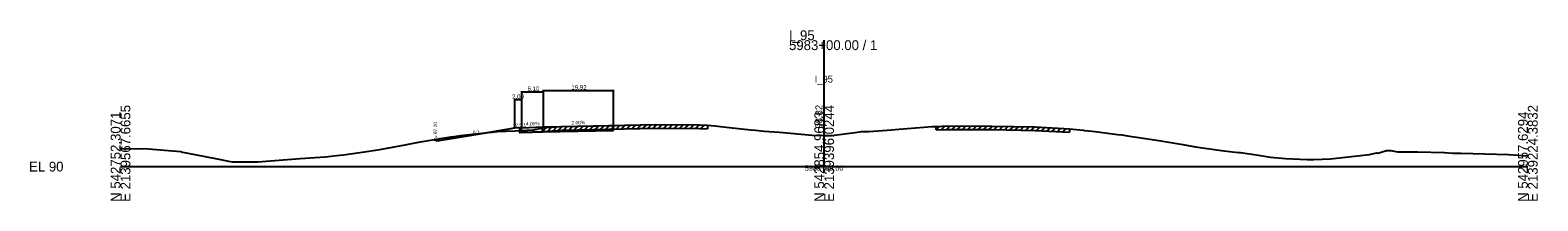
# Model space of a CAD drawing. Extents: x -12534 to 3403, y -1332 to 21983.
# Drawn here: x -25.7 to 402.8, y 14990.3 to 15038.7 of the extents above; entities that cross this region are included whole.
import ezdxf

# ---------------------------------------------------------------- set-up
doc = ezdxf.new("R2010")
doc.units = 0
for name, color, linetype in [('RD_GPK_XS_Cell', 7, 'Continuous'), ('RD_XD_TX_Width', 7, 'Continuous'), ('RD_XS_Base', 7, 'Continuous'), ('RD_XS_EarthShd', 7, 'Continuous'), ('RD_XS_EwShp', 7, 'Continuous'), ('RD_XS_ExGround', 7, 'Continuous'), ('RD_XS_ExPaveRet', 7, 'Continuous'), ('RD_XS_OSBase', 7, 'Continuous'), ('RD_XS_Pave', 7, 'Continuous'), ('RD_XS_TieSlope', 7, 'Continuous'), ('RD_XS_TX_Baseline', 7, 'Continuous'), ('RD_XS_TX_Elev_EX', 7, 'Continuous'), ('RD_XS_TX_Elev_PR', 7, 'Continuous'), ('RD_XS_TX_ShdSlope', 7, 'Continuous'), ('RD_XS_TX_Slope', 7, 'Continuous'), ('RD_XS_TX_Station', 7, 'Continuous')]:
    doc.layers.add(name, color=color, linetype=linetype)

msp = doc.modelspace()

# ---------------------------------------------------------------- linework, layer by layer
at = {"layer": 'RD_GPK_XS_Cell'}
for p, q in [((200, 15000), (200, 15035.85)), ((0, 15000), (200, 15000)), ((200, 15000), (400, 15000))]:
    msp.add_line(p, q, dxfattribs=at)
at = {"layer": 'RD_XD_TX_Width'}
for p, q in [((113.98, 15021.42), (113.98, 15011.23)), ((113.98, 15021.22), (120.08, 15021.22)), ((120.08, 15021.82), (120.08, 15011.47)), ((120.08, 15021.62), (140, 15021.62)), ((120.08, 15021.42), (120.08, 15011.47)), ((140, 15021.82), (140, 15011.87)), ((111.98, 15019.18), (111.98, 15011.07)), ((113.98, 15018.98), (111.98, 15018.98)), ((113.98, 15019.18), (113.98, 15011.23))]:
    msp.add_line(p, q, dxfattribs=at)
at = {"layer": 'RD_XS_Base'}
for p, q in [((113.98, 15009.63), (120.08, 15009.87)), ((120.08, 15009.87), (140, 15010.27))]:
    msp.add_line(p, q, dxfattribs=at)
at = {"layer": 'RD_XS_EarthShd'}
msp.add_line((113.98, 15011.03), (111.98, 15010.87), dxfattribs=at)
at = {"layer": 'RD_XS_EwShp'}
for points in [[(113.98, 15009.63), (113.48, 15009.61), (113.48, 15010.22), (117.47, 15010.47), (119.93, 15010.98), (125.46, 15011.34), (140, 15011.67), (140, 15011.27), (140, 15010.27), (120.08, 15009.87)], [(93.84, 15008.43), (94.79, 15008.58), (96.67, 15008.78), (105.23, 15009.78), (105.65, 15009.81), (89.98, 15007.2), (89.13, 15007.63), (90.93, 15007.93)], [(113.48, 15010.22), (113.48, 15010.61), (113.98, 15010.63), (113.98, 15011.03), (111.98, 15010.87), (105.65, 15009.81), (107.1, 15009.93), (112.14, 15010.13)]]:
    msp.add_lwpolyline(points, close=True, dxfattribs=at)
at = {"layer": 'RD_XS_ExGround'}
msp.add_lwpolyline([(0, 15005.03), (6.83, 15005.15), (13.67, 15004.58), (17.12, 15004.26), (17.64, 15004.1), (21.07, 15003.46), (27.5, 15002.16), (30.72, 15001.53), (31.85, 15001.37), (35.82, 15001.36), (39.02, 15001.32), (51.02, 15002.29), (58.19, 15002.8), (62.32, 15003.2), (63.35, 15003.33), (68.72, 15004.08), (73.73, 15004.87), (80.9, 15006.19), (84.23, 15006.81), (85.87, 15007.09), (90.93, 15007.93), (93.84, 15008.43), (94.79, 15008.58), (96.67, 15008.78), (105.23, 15009.78), (107.1, 15009.93), (112.14, 15010.13), (117.47, 15010.47), (119.93, 15010.98), (125.46, 15011.34), (152.11, 15011.95), (164.56, 15011.83), (166.87, 15011.73), (168.93, 15011.56), (172.98, 15011.11), (179.13, 15010.44), (180.48, 15010.32), (182.96, 15010.09), (187.25, 15009.73), (196.61, 15008.93), (200.27, 15008.81), (202.06, 15008.82), (208.8, 15009.69), (210.61, 15009.94), (211.55, 15009.99), (212.81, 15009.99), (219.15, 15010.46), (221.24, 15010.62), (228.34, 15011.21), (230.72, 15011.39), (231.8, 15011.42), (235.1, 15011.55), (247.68, 15011.51), (259.95, 15011.28), (269.69, 15010.74), (273.62, 15010.35), (273.98, 15010.29), (275.19, 15010.19), (277.05, 15010), (283.41, 15009.14), (284.58, 15009), (286.23, 15008.71), (295.07, 15007.42), (301.92, 15006.26), (305.51, 15005.64), (312.92, 15004.59), (316.01, 15004.17), (317.87, 15004), (318.33, 15003.96), (323.44, 15003.24), (326.81, 15002.7), (331.13, 15002.28), (337.26, 15002.05), (339.19, 15002.06), (343.94, 15002.22), (354.96, 15003.44), (357, 15003.94), (357.39, 15003.81), (359.78, 15004.58), (360.23, 15004.6), (361.04, 15004.54), (362.98, 15004.18), (368.66, 15004.22), (376.34, 15004.02), (378.68, 15003.82), (379.47, 15003.82), (381.03, 15003.8), (394.46, 15003.41), (400, 15003.05)], dxfattribs=at)
at = {"layer": 'RD_XS_ExPaveRet'}
for p, q in [((131.93, 15010.49), (132.95, 15011.51)), ((133.43, 15010.52), (134.45, 15011.54)), ((134.93, 15010.56), (135.95, 15011.58)), ((136.43, 15010.59), (137.45, 15011.61)), ((137.93, 15010.62), (138.95, 15011.65)), ((139.43, 15010.66), (140.45, 15011.68)), ((140.93, 15010.69), (141.95, 15011.72)), ((142.43, 15010.73), (143.45, 15011.75)), ((143.93, 15010.76), (144.95, 15011.79)), ((145.43, 15010.8), (146.45, 15011.82)), ((146.93, 15010.83), (147.95, 15011.85)), ((148.43, 15010.86), (149.45, 15011.89)), ((149.93, 15010.9), (150.95, 15011.92)), ((151.43, 15010.93), (152.44, 15011.95)), ((152.93, 15010.94), (153.92, 15011.93)), ((154.43, 15010.93), (155.42, 15011.92)), ((155.93, 15010.91), (156.92, 15011.9)), ((157.43, 15010.9), (158.42, 15011.89)), ((158.93, 15010.88), (159.92, 15011.87)), ((160.43, 15010.87), (161.42, 15011.86)), ((161.93, 15010.85), (162.92, 15011.84)), ((163.43, 15010.84), (164.42, 15011.83)), ((164.93, 15010.81), (165.89, 15011.77)), ((166.87, 15011.73), (166.87, 15010.73)), ((233.3, 15010.48), (234.34, 15011.52)), ((234.8, 15010.54), (235.81, 15011.55)), ((236.3, 15010.55), (237.29, 15011.55)), ((237.8, 15010.54), (238.79, 15011.54)), ((239.3, 15010.54), (240.29, 15011.54)), ((240.8, 15010.53), (241.79, 15011.53)), ((242.3, 15010.53), (243.29, 15011.53)), ((243.8, 15010.53), (244.79, 15011.52)), ((245.3, 15010.52), (246.29, 15011.52)), ((246.8, 15010.52), (247.79, 15011.51)), ((119.93, 15009.98), (121, 15011.05)), ((119.93, 15009.98), (119.93, 15010.98)), ((119.93, 15009.98), (125.46, 15010.34)), ((121.43, 15010.08), (122.5, 15011.15)), ((122.93, 15010.18), (124, 15011.24)), ((124.43, 15010.27), (125.5, 15011.34)), ((125.46, 15010.34), (152.11, 15010.95)), ((125.93, 15010.35), (126.95, 15011.37)), ((127.43, 15010.38), (128.45, 15011.41)), ((128.93, 15010.42), (129.95, 15011.44)), ((130.43, 15010.45), (131.45, 15011.48)), ((152.11, 15010.95), (164.56, 15010.83)), ((164.56, 15010.83), (166.87, 15010.73)), ((231.8, 15010.42), (232.84, 15011.46)), ((231.8, 15010.42), (231.8, 15011.42)), ((231.8, 15010.42), (235.1, 15010.55)), ((235.1, 15010.55), (247.68, 15010.51)), ((247.68, 15010.51), (259.95, 15010.28)), ((248.3, 15010.5), (249.28, 15011.48)), ((249.8, 15010.47), (250.78, 15011.46)), ((251.3, 15010.45), (252.28, 15011.43)), ((252.8, 15010.42), (253.78, 15011.4)), ((254.3, 15010.39), (255.28, 15011.37)), ((255.8, 15010.36), (256.78, 15011.34)), ((257.3, 15010.33), (258.28, 15011.31)), ((258.8, 15010.3), (259.78, 15011.29)), ((259.95, 15010.28), (269.69, 15009.74)), ((260.3, 15010.26), (261.25, 15011.21)), ((261.8, 15010.18), (262.75, 15011.13)), ((263.3, 15010.1), (264.25, 15011.04)), ((264.8, 15010.01), (265.75, 15010.96)), ((266.3, 15009.93), (267.25, 15010.88)), ((267.8, 15009.85), (268.75, 15010.79)), ((269.69, 15010.74), (269.69, 15009.74))]:
    msp.add_line(p, q, dxfattribs=at)
at = {"layer": 'RD_XS_OSBase'}
for p, q in [((140, 15011.27), (140, 15011.67)), ((113.48, 15010.61), (113.98, 15010.63)), ((113.48, 15009.61), (113.48, 15010.61)), ((113.98, 15009.63), (113.48, 15009.61)), ((113.98, 15010.63), (113.98, 15011.03)), ((140, 15010.27), (140, 15011.27))]:
    msp.add_line(p, q, dxfattribs=at)
at = {"layer": 'RD_XS_Pave'}
for p, q in [((120.08, 15011.27), (140, 15011.67)), ((113.98, 15011.03), (120.08, 15011.27))]:
    msp.add_line(p, q, dxfattribs=at)
at = {"layer": 'RD_XS_TieSlope'}
for p, q in [((89.98, 15007.2), (89.13, 15007.63)), ((111.98, 15010.87), (89.98, 15007.2))]:
    msp.add_line(p, q, dxfattribs=at)

# ---------------------------------------------------------------- texts
at = {"layer": 'RD_GPK_XS_Cell'}
for s, p in [('I_95', (190, 15035.85)), ('5983+00.00 / 1', (190, 15033.05)), ('EL 90', (-26, 14998.6))]:
    msp.add_text(s, height=2.8, dxfattribs=at).set_placement(p)
for s, p in [('E 2139567.6655', (2.8, 14990)), ('E 2139396.0244', (202.8, 14990)), ('E 2139224.3832', (402.8, 14990)), ('N 542752.3071', (0, 14990)), ('N 542854.9683', (200, 14990)), ('N 542957.6294', (400, 14990))]:
    msp.add_text(s, height=2.8, rotation=90, dxfattribs=at).set_placement(p)
at = {"layer": 'RD_XD_TX_Width'}
for s, p in [('2.00', (111.29, 15019.23)), ('6.10', (115.68, 15021.47)), ('19.92', (128.14, 15021.87))]:
    msp.add_text(s, height=1.25, dxfattribs=at).set_placement(p)
at = {"layer": 'RD_XS_TX_Baseline'}
msp.add_text('I_95', height=2, dxfattribs=at).set_placement((197.28, 15023.82))
at = {"layer": 'RD_XS_TX_Elev_EX'}
msp.add_text('98.82', height=2, rotation=90, dxfattribs=at).set_placement((199.5, 15010.82))
at = {"layer": 'RD_XS_TX_Elev_PR'}
msp.add_text('97.20', height=1, rotation=90, dxfattribs=at).set_placement((89.98, 15009.2))
at = {"layer": 'RD_XS_TX_ShdSlope'}
msp.add_text('12.5:1', height=1, rotation=4.5739, dxfattribs=at).set_placement((111.45, 15011.08))
msp.add_text('12.5:1', height=1, rotation=4.5739, dxfattribs=at).set_placement((111.45, 15011.08))
at = {"layer": 'RD_XS_TX_Slope'}
for s, rotation, p in [('4.00%', 2.2906, (115.21, 15011.58)), ('2.00%', 1.1458, (128.18, 15011.94)), ('2:1', 333.4349, (88.99, 15007.98)), ('6:1', 9.4623, (100.24, 15009.17))]:
    msp.add_text(s, height=1, rotation=rotation, dxfattribs=at).set_placement(p)
at = {"layer": 'RD_XS_TX_Station'}
msp.add_text('5983+00.00', height=1.5, dxfattribs=at).set_placement((194.48, 14998.82))

doc.saveas('drawing.dxf')
